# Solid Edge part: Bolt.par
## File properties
Author: Sarvanan
Template: Sync Iso Part.par
Last saved by: CADCIM
Revision: 16
Application: Solid Edge
Accuracy: 0.990
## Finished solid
Body 1: solid body, 12 faces, 22 edges, 12 vertices.
  Faces by surface: plane 7, spun 4, cylinder 1
  Edges by curve: line 8, circle 7, intersection 7
Bounding box of the edges (mm; curved faces can reach further): 24.000 x 24.000 x 104.000, from (0, -2.3071, 0) to (24, 21.6929, 104).
Cylindrical faces by radius (mm): R6 x1
Planar faces by outward normal: +x 1, +y 1, +z 2, -x 1, -y 1, -z 1
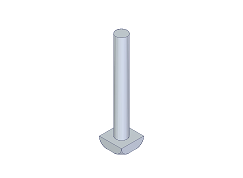
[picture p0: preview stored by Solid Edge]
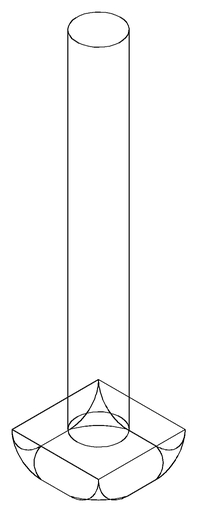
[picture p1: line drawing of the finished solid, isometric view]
